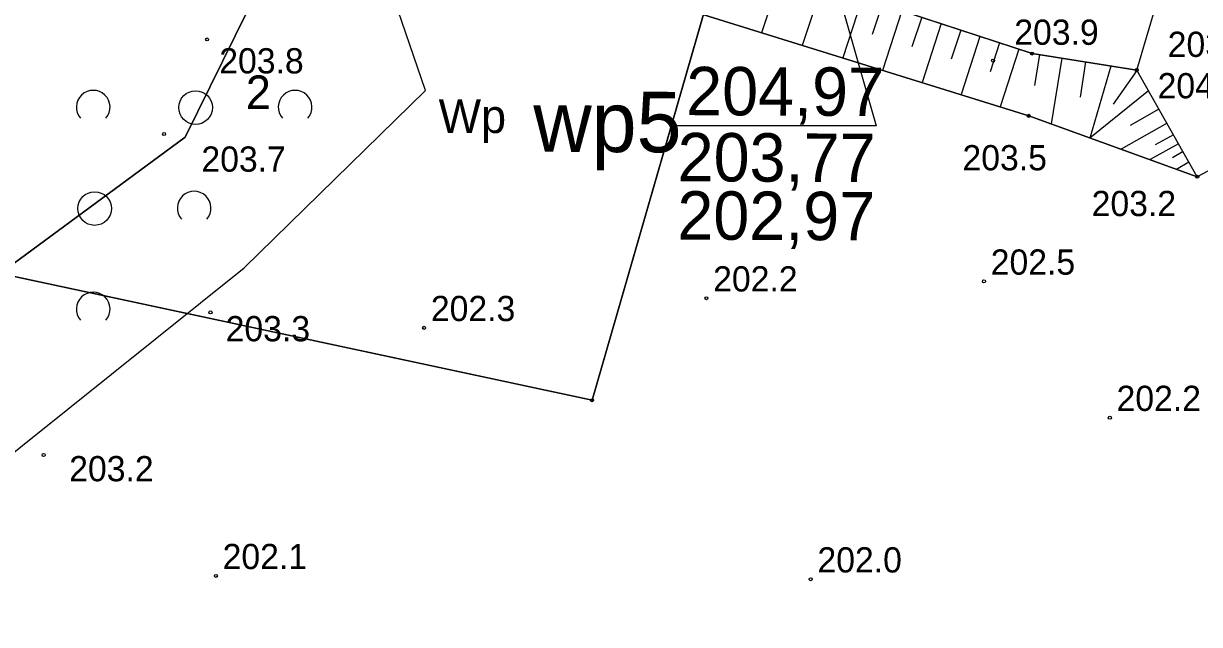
# Model space of a CAD drawing. Extents: x 6512606 to 6513006, y 6022524 to 6022728.
# Drawn here: x 6512758.91 to 6512793.86, y 6022557.42 to 6022575.27 of the extents above; entities that cross this region are included whole.
import ezdxf

# ---------------------------------------------------------------- set-up
doc = ezdxf.new("R2010")
doc.units = 0
for name, color, linetype in [('000 Inne (niezydentyfikowane)', 7, 'Continuous'), ('20', 7, 'Continuous'), ('203-punkt graniczny', 7, 'Continuous'), ('210-oznaczenie konturu użytku gruntowego', 7, 'Continuous'), ('211-numer działki ewidencyjnej', 7, 'Continuous'), ('216-obręb ewidencyjny', 7, 'Continuous'), ('218-kontur użytku gruntowego', 7, 'Continuous'), ('219-działka ewidencyjna', 7, 'Continuous'), ('4', 7, 'Continuous'), ('Default', 7, 'Continuous'), ('Level 47', 7, 'Continuous'), ('pikieta naturalna', 7, 'Continuous'), ('pikieta naturalna-Atr2', 7, 'Continuous'), ('punkt wysokościowy naturalny', 7, 'Continuous'), ('punkt wysokościowy naturalny-Atr2', 7, 'Continuous'), ('skarpa nieumocniona', 7, 'Continuous'), ('woda stojąca', 7, 'Continuous'), ('zadrzewienie  zakrzewienie', 7, 'Continuous')]:
    doc.layers.add(name, color=color, linetype=linetype)

# ---------------------------------------------------------------- blocks, each defined once
blk = doc.blocks.new('203')
at = {"layer": 'Default'}
blk.add_circle((0, 0), 0.45, dxfattribs=at)
blk = doc.blocks.new('PW01')
at = {"layer": 'Default'}
blk.add_circle((0, 0), 0.45, dxfattribs=at)
blk = doc.blocks.new('OTZK1')
at = {"layer": 'Default'}
blk.add_circle((0, 0), 5, dxfattribs=at)
blk = doc.blocks.new('OTZK2')
at = {"layer": 'Default'}
blk.add_arc((0, 0), 5, 318.85, 221.162, dxfattribs=at)

msp = doc.modelspace()

# ---------------------------------------------------------------- linework, layer by layer
at = {"layer": '000 Inne (niezydentyfikowane)'}
for points in [[(6512781.45, 6022576.82), (6512780.85, 6022575)], [(6512782.65, 6022576.42), (6512782.06, 6022574.62)], [(6512783.84, 6022576.03), (6512783.26, 6022574.25)], [(6512784.43, 6022575.84), (6512784.14, 6022574.95)], [(6512785.02, 6022575.65), (6512784.44, 6022573.88)], [(6512785.61, 6022575.46), (6512785.32, 6022574.58)], [(6512786.19, 6022575.27), (6512785.62, 6022573.52)], [(6512786.77, 6022575.08), (6512786.48, 6022574.21)], [(6512787.34, 6022574.89), (6512786.78, 6022573.16)], [(6512787.92, 6022574.7), (6512787.64, 6022573.84)], [(6512788.5, 6022574.51), (6512787.94, 6022572.8)], [(6512789.11, 6022574.35), (6512788.96, 6022573.43)], [(6512789.77, 6022574.24), (6512789.46, 6022572.29)], [(6512790.48, 6022574.13), (6512790.32, 6022573.08)], [(6512791.23, 6022574.01), (6512790.61, 6022571.87)], [(6512792, 6022573.88), (6512791.3, 6022572.88)], [(6512792.35, 6022573.27), (6512790.61, 6022571.87)], [(6512792.66, 6022572.73), (6512791.8, 6022572.24)], [(6512792.9, 6022572.31), (6512791.54, 6022571.54)], [(6512793.09, 6022571.97), (6512792.55, 6022571.67)], [(6512793.24, 6022571.7), (6512792.4, 6022571.23)], [(6512793.38, 6022571.47), (6512793.06, 6022571.28)], [(6512793.55, 6022571.15), (6512793.18, 6022570.94)]]:
    msp.add_lwpolyline(points, dxfattribs=at)
at = {"layer": '20'}
for p, q in [((6512778.758, 6022591.427), (6512784.26, 6022572.235)), ((6512784.26, 6022572.235), (6512778.325, 6022572.235))]:
    msp.add_line(p, q, dxfattribs=at)
at = {"layer": '216-obręb ewidencyjny'}
for points in [[(6512728.286, 6022540.131), (6512737.69, 6022552.74), (6512751.08, 6022569.37), (6512775.81, 6022564.08), (6512780.7, 6022581.02), (6512806.2, 6022572.11), (6512806.62, 6022563.51), (6512811.41, 6022558.95), (6512818.47, 6022559.72), (6512828.23, 6022562.62), (6512858.85, 6022571.74), (6512855.78, 6022583.95), (6512853.17, 6022604.51), (6512852.25, 6022608.25), (6512838.47, 6022634.29)], [(6512824.714, 6022553.406), (6512818.47, 6022559.72), (6512811.41, 6022558.95), (6512806.62, 6022563.51), (6512806.2, 6022572.11), (6512780.7, 6022581.02), (6512775.81, 6022564.08), (6512751.08, 6022569.37)]]:
    msp.add_lwpolyline(points, dxfattribs=at)
at = {"layer": '218-kontur użytku gruntowego'}
for points in [[(6512763.72, 6022571.9), (6512767.43, 6022579.43)], [(6512767.43, 6022579.43), (6512763.72, 6022571.9)], [(6512775.81, 6022564.08), (6512779.89, 6022578.2)], [(6512779.89, 6022578.2), (6512775.81, 6022564.08)], [(6512758.21, 6022567.84), (6512763.72, 6022571.9)], [(6512763.72, 6022571.9), (6512758.21, 6022567.84)], [(6512758.21, 6022567.84), (6512775.81, 6022564.08)], [(6512775.81, 6022564.08), (6512758.21, 6022567.84)]]:
    msp.add_lwpolyline(points, dxfattribs=at)
at = {"layer": '219-działka ewidencyjna'}
for points in [[(6512780.7, 6022581.02), (6512775.81, 6022564.08)], [(6512775.81, 6022564.08), (6512751.08, 6022569.37)]]:
    msp.add_lwpolyline(points, dxfattribs=at)
at = {"layer": '4'}
for points in [[(6512780.7, 6022581.02), (6512775.81, 6022564.08)], [(6512775.81, 6022564.08), (6512751.08, 6022569.37)]]:
    msp.add_lwpolyline(points, dxfattribs=at)
at = {"layer": 'skarpa nieumocniona'}
msp.add_lwpolyline([(6512771.62, 6022580.04), (6512772.41, 6022579.75), (6512775.8, 6022576.99), (6512778.27, 6022575.8), (6512788.79, 6022572.53), (6512793.8, 6022570.72), (6512792, 6022573.89), (6512788.89, 6022574.38)], close=True, dxfattribs=at)
msp.add_lwpolyline([(6512771.62, 6022580.04), (6512772.41, 6022579.75), (6512775.8, 6022576.99), (6512778.27, 6022575.8), (6512788.79, 6022572.53), (6512793.8, 6022570.72), (6512792, 6022573.89), (6512788.89, 6022574.38)], close=True, dxfattribs=at)
at = {"layer": 'woda stojąca'}
for points in [[(6512822.08, 6022551.38), (6512805.27, 6022559.18), (6512802.35, 6022567.67), (6512799.36, 6022570.79), (6512795.57, 6022571.66), (6512793.8, 6022570.72), (6512788.79, 6022572.53), (6512778.27, 6022575.8), (6512775.8, 6022576.99), (6512772.41, 6022579.75), (6512771.62, 6022580.04), (6512770.3, 6022579.81), (6512769.49, 6022580.02), (6512768.52, 6022578.94)], [(6512741.02, 6022546.93), (6512746.68, 6022552.11), (6512753.93, 6022559.53), (6512757.57, 6022561.69), (6512765.47, 6022568.01), (6512770.86, 6022573.28), (6512769.34, 6022577.71), (6512768.52, 6022578.94)]]:
    msp.add_lwpolyline(points, dxfattribs=at)
at = {"layer": 'zadrzewienie  zakrzewienie'}
msp.add_lwpolyline([(6512757.57, 6022561.69), (6512765.47, 6022568.01), (6512770.86, 6022573.28), (6512769.34, 6022577.71), (6512768.52, 6022578.94), (6512769.49, 6022580.02), (6512770.3, 6022579.81), (6512771.62, 6022580.04), (6512773.43, 6022579.45), (6512788.89, 6022574.38), (6512792, 6022573.89), (6512792.58, 6022575.83), (6512790.41, 6022579.36), (6512788.13, 6022581.61), (6512782.6, 6022584.18), (6512782.06, 6022584.86), (6512781.1, 6022585.98), (6512776.87, 6022587.41), (6512770, 6022592.05), (6512764.51, 6022594.96), (6512748.08, 6022603.68)], dxfattribs=at)

# ---------------------------------------------------------------- block references
at = {"layer": '203-punkt graniczny', "xscale": 0.1, "yscale": 0.10000000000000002}
msp.add_blockref('203', (6512775.81, 6022564.08), dxfattribs=at)
at = {"layer": 'pikieta naturalna', "xscale": 0.1, "yscale": 0.10000000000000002}
for p in [(6512788.89, 6022574.38), (6512792, 6022573.89), (6512788.79, 6022572.53), (6512793.8, 6022570.72), (6512787.46, 6022567.61), (6512779.21, 6022567.11), (6512764.47, 6022566.69), (6512770.82, 6022566.23), (6512791.2, 6022563.56), (6512759.51, 6022562.45), (6512764.63, 6022558.86), (6512782.31, 6022558.76)]:
    msp.add_blockref('PW01', p, dxfattribs=at)
at = {"layer": 'punkt wysokościowy naturalny', "xscale": 0.1, "yscale": 0.10000000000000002}
for p in [(6512764.37, 6022574.8), (6512787.73, 6022574.17), (6512763.09, 6022571.99)]:
    msp.add_blockref('PW01', p, dxfattribs=at)
at = {"layer": 'zadrzewienie  zakrzewienie', "xscale": 0.1, "yscale": 0.10000000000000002}
for name, p in [('OTZK2', (6512760.984, 6022572.787)), ('OTZK1', (6512764.026, 6022572.776)), ('OTZK2', (6512766.984, 6022572.787)), ('OTZK1', (6512761.026, 6022569.776)), ('OTZK2', (6512763.984, 6022569.787)), ('OTZK2', (6512760.984, 6022566.787))]:
    msp.add_blockref(name, p, dxfattribs=at)

# ---------------------------------------------------------------- texts
at = {"layer": '210-oznaczenie konturu użytku gruntowego'}
msp.add_text('Wp', height=1, dxfattribs=at).set_placement((6512771.25, 6022572.02))
at = {"layer": '211-numer działki ewidencyjnej'}
msp.add_text('2', height=1, dxfattribs=at).set_placement((6512765.52, 6022572.73))
at = {"layer": '4'}
msp.add_text('2', height=1, dxfattribs=at).set_placement((6512765.52, 6022572.73))
at = {"layer": 'Level 47'}
for s, height, p in [('204,97', 1.4377, (6512778.605, 6022572.551)), ('wp5', 1.7971, (6512774.059, 6022571.465)), ('203,77', 1.4377, (6512778.351, 6022570.587)), ('202,97', 1.4377, (6512778.343, 6022568.855))]:
    msp.add_text(s, height=height, rotation=359.7281, dxfattribs=at).set_placement(p)
at = {"layer": 'pikieta naturalna-Atr2'}
for s, p in [('203.7', (6512792.92, 6022574.28)), ('204.0', (6512792.62, 6022573.05)), ('203.5', (6512786.82, 6022570.91)), ('203.2', (6512790.66, 6022569.55)), ('202.5', (6512787.66, 6022567.81)), ('202.2', (6512779.41, 6022567.31)), ('202.3', (6512771.02, 6022566.43)), ('203.3', (6512764.92, 6022565.83)), ('202.2', (6512791.4, 6022563.76)), ('203.2', (6512760.27, 6022561.67)), ('202.1', (6512764.83, 6022559.06)), ('202.0', (6512782.51, 6022558.96))]:
    msp.add_text(s, height=0.75, dxfattribs=at).set_placement(p)
at = {"layer": 'punkt wysokościowy naturalny-Atr2'}
for s, p in [('203.9', (6512788.36, 6022574.64)), ('203.8', (6512764.73, 6022573.79)), ('203.7', (6512764.2, 6022570.87))]:
    msp.add_text(s, height=0.75, dxfattribs=at).set_placement(p)

doc.saveas('drawing.dxf')
